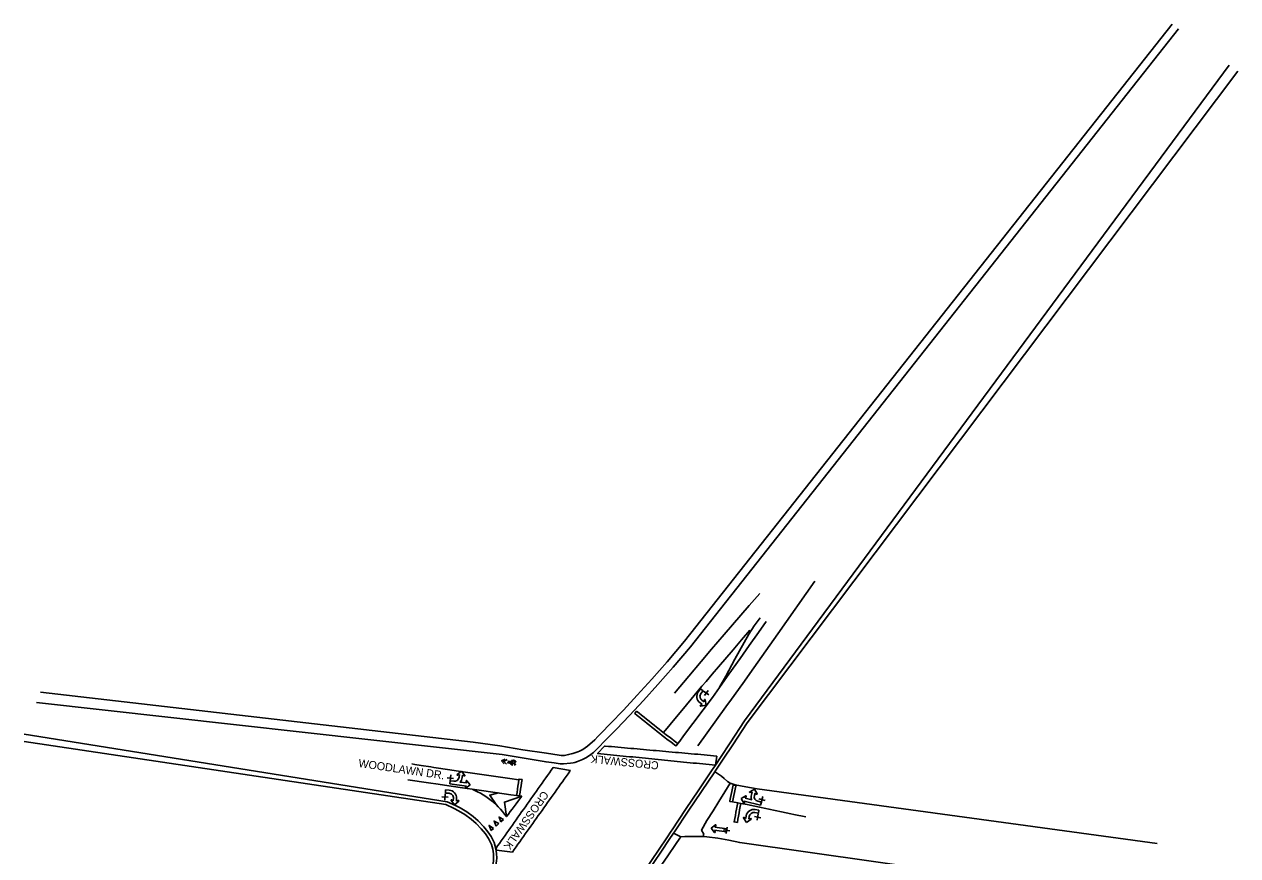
# Model space of a CAD drawing. Extents: x 1729281 to 1732101, y 650763 to 653805.
# Drawn here: x 1730328 to 1731086, y 653286 to 653805 of the extents above; entities that cross this region are included whole.
import ezdxf

# ---------------------------------------------------------------- set-up
doc = ezdxf.new("R2010")
doc.units = 0
for name, color, linetype in [('SURVEY - ROADSIDE BARRIERS with Text', 7, 'Continuous'), ('SURVEY - TRAFFIC CONTROL - Pavement Marking - Points - Locators', 7, 'Continuous'), ('SURVEY - TRAFFIC CONTROL - Pavement Marking with Text', 7, 'Continuous'), ('SURVEY - TRANSPORTATION - Features', 7, 'Continuous'), ('SURVEY - TRANSPORTATION - Roads', 7, 'Continuous'), ('SURVEY - TRANSPORTATION - Roads Text', 7, 'Continuous')]:
    doc.layers.add(name, color=color, linetype=linetype)

msp = doc.modelspace()

# ---------------------------------------------------------------- linework, layer by layer
at = {"layer": 'SURVEY - ROADSIDE BARRIERS with Text'}
for points in [[(1730663.16, 653348.86), (1730665.26, 653348.91), (1730667.81, 653349.44), (1730669.47, 653349.82), (1730670.44, 653350.07), (1730671.64, 653350.44), (1730673.67, 653351.24), (1730674.6, 653351.61), (1730676.69, 653352.62), (1730679.7, 653354.72), (1730684.19, 653358.62), (1730686.11, 653360.64), (1730688.16, 653362.79), (1730694.02, 653368.8), (1730702.16, 653377.27), (1730710.73, 653386.5), (1730719.92, 653396.51), (1730729.49, 653407.31), (1730740.14, 653420.16), (1731044.8, 653805.48)], [(1731085.84, 653776.25), (1730779.43, 653369.32), (1730770.36, 653355.57), (1730764.42, 653346.65), (1730759.8, 653339.63), (1730759.25, 653338.77), (1730750.93, 653326.43), (1730742.52, 653314.01), (1730734.03, 653301.24), (1730733.39, 653300.36), (1730730.72, 653296.31), (1730725.93, 653289.21), (1730716.21, 653275.07)], [(1730337.82, 653388.41), (1730608.3, 653357.12), (1730624.79, 653354.98), (1730639.27, 653352.49), (1730654.1, 653350.23), (1730661.91, 653349.02), (1730663.16, 653348.86)], [(1730614.71, 653267.4), (1730616.59, 653270.23), (1730617.64, 653272.3), (1730618.98, 653275.43), (1730619.91, 653278.38), (1730620.45, 653280.88), (1730620.86, 653282.91), (1730620.96, 653284.51), (1730620.97, 653287.52), (1730620.53, 653290.44), (1730619.7, 653293.26), (1730617.79, 653297.02), (1730615.82, 653299.96), (1730613.2, 653303.08), (1730610.03, 653306.4), (1730606.9, 653309.12), (1730602.9, 653312.06), (1730599.11, 653314.37), (1730596.37, 653315.86), (1730591.15, 653318.2), (1730327.77, 653357.56)], [(1730768.85, 653331.69), (1730771.9, 653330.52), (1730778.64, 653329.27), (1730785.53, 653328.14), (1731035.47, 653293.97)], [(1730751.98, 653298.19), (1730754.27, 653298.03), (1730761.02, 653297.22), (1730767.88, 653295.95), (1730774.71, 653294.52), (1731029.66, 653258.33)]]:
    msp.add_lwpolyline(points, dxfattribs=at)
at = {"layer": 'SURVEY - TRAFFIC CONTROL - Pavement Marking - Points - Locators'}
for p, q in [((1730752.63, 653386.28), (1730754.98, 653389.52)), ((1730755.42, 653386.72), (1730752.19, 653389.08)), ((1730594.26, 653336.74), (1730593.75, 653332.77)), ((1730595.99, 653334.51), (1730592.02, 653335.01)), ((1730592.68, 653322.84), (1730588.68, 653323.09)), ((1730590.8, 653324.96), (1730590.56, 653320.97)), ((1730786.73, 653321.83), (1730790.6, 653320.83)), ((1730788.16, 653319.4), (1730789.16, 653323.27)), ((1730783.99, 653310.74), (1730787.92, 653310.04)), ((1730785.6, 653308.42), (1730786.31, 653312.36)), ((1730764.59, 653302.42), (1730768.56, 653301.89)), ((1730766.31, 653300.17), (1730766.84, 653304.14))]:
    msp.add_line(p, q, dxfattribs=at)
at = {"layer": 'SURVEY - TRAFFIC CONTROL - Pavement Marking with Text'}
for p, q in [((1730750.22, 653390.5), (1730748.87, 653388.65)), ((1730751.81, 653389.35), (1730750.22, 653390.5)), ((1730751.81, 653389.35), (1730750.46, 653387.49)), ((1730751.12, 653383.37), (1730752.42, 653382.42)), ((1730752.42, 653382.42), (1730752.71, 653383.61)), ((1730753.72, 653380.26), (1730753.19, 653383.59)), ((1730749.96, 653381.77), (1730751.27, 653380.82)), ((1730751.27, 653380.82), (1730750.22, 653380.18)), ((1730753.72, 653380.26), (1730750.38, 653379.73)), ((1730600.84, 653339.1), (1730598.17, 653337.03)), ((1730599.57, 653336.92), (1730598.38, 653336.6)), ((1730599.36, 653335.32), (1730599.57, 653336.92)), ((1730600.84, 653339.1), (1730602.91, 653336.43)), ((1730601.32, 653335.07), (1730601.52, 653336.68)), ((1730601.52, 653336.68), (1730602.59, 653336.07)), ((1730593.79, 653333.05), (1730593.54, 653331.1)), ((1730593.54, 653331.1), (1730603.97, 653329.77)), ((1730593.79, 653333.05), (1730596.06, 653332.76)), ((1730599.97, 653332.27), (1730604.22, 653331.73)), ((1730603.97, 653329.77), (1730603.36, 653328.71)), ((1730606.39, 653330.46), (1730603.72, 653328.39)), ((1730604.22, 653331.73), (1730603.9, 653332.91)), ((1730606.39, 653330.46), (1730604.33, 653333.13)), ((1730590.83, 653325.42), (1730590.95, 653327.38)), ((1730590.83, 653325.42), (1730593.12, 653325.28)), ((1730590.95, 653327.38), (1730593.24, 653327.24)), ((1730595.89, 653322.15), (1730595.79, 653320.54)), ((1730597.85, 653322.03), (1730597.75, 653320.42)), ((1730638.59, 653323.42), (1730637.1, 653323.63)), ((1730775.56, 653321.95), (1730778.47, 653323.66)), ((1730775.56, 653321.95), (1730777.28, 653319.04)), ((1730778.06, 653322.32), (1730778.8, 653323.3)), ((1730782.2, 653321.25), (1730778.06, 653322.32)), ((1730783.93, 653327.91), (1730781.02, 653326.2)), ((1730782.4, 653325.92), (1730781.18, 653325.75)), ((1730781.99, 653324.35), (1730782.4, 653325.92)), ((1730783.9, 653323.86), (1730784.3, 653325.42)), ((1730783.93, 653327.91), (1730785.64, 653325)), ((1730784.3, 653325.42), (1730785.28, 653324.68)), ((1730596.63, 653318.16), (1730594.39, 653320.69)), ((1730595.79, 653320.54), (1730594.68, 653321.08)), ((1730596.63, 653318.16), (1730599.16, 653320.4)), ((1730597.75, 653320.42), (1730598.92, 653320.82)), ((1730770.28, 653319.9), (1730773.54, 653319.32)), ((1730787.74, 653317.78), (1730777.56, 653320.42)), ((1730777.56, 653320.42), (1730777.73, 653319.2)), ((1730786.73, 653314.75), (1730784.47, 653315.15)), ((1730788.24, 653319.68), (1730786.01, 653320.26)), ((1730786.39, 653312.81), (1730786.73, 653314.75)), ((1730788.24, 653319.68), (1730787.74, 653317.78)), ((1730624.25, 653306.31), (1730622.47, 653304.75)), ((1730627.21, 653308.93), (1730625.49, 653307.41)), ((1730779.04, 653307.13), (1730777.11, 653309.9)), ((1730778.48, 653309.58), (1730777.45, 653310.25)), ((1730778.77, 653311.18), (1730778.48, 653309.58)), ((1730779.04, 653307.13), (1730781.81, 653309.06)), ((1730780.7, 653310.83), (1730780.42, 653309.24)), ((1730780.42, 653309.24), (1730781.62, 653309.5)), ((1730786.39, 653312.81), (1730784.13, 653313.22)), ((1730620.9, 653303.36), (1730619.51, 653302.13)), ((1730756.82, 653303.47), (1730759.51, 653305.52)), ((1730756.82, 653303.47), (1730758.87, 653300.79)), ((1730766.44, 653301.18), (1730758.99, 653302.19)), ((1730758.99, 653302.19), (1730759.3, 653301)), ((1730759.25, 653304.14), (1730759.87, 653305.2)), ((1730766.71, 653303.13), (1730759.25, 653304.14)), ((1730766.44, 653301.18), (1730766.71, 653303.13))]:
    msp.add_line(p, q, dxfattribs=at)
for points in [[(1730748.51, 653354.94), (1730754.39, 653363.03), (1730766.12, 653379.23), (1730769.64, 653384.09), (1730776.66, 653393.82), (1730783.54, 653403.64), (1730798.47, 653424.93), (1730821.64, 653457.63)], [(1730733.93, 653387.8), (1730742.97, 653398.49), (1730750.73, 653407.64), (1730757.2, 653415.26), (1730764.98, 653424.4), (1730766.29, 653425.91), (1730768.92, 653428.92), (1730770.23, 653430.43), (1730780.73, 653442.5), (1730787.33, 653450.08)], [(1730762.17, 653391.45), (1730766.15, 653398.39), (1730771.64, 653409.05), (1730777.53, 653419.51), (1730780.52, 653424.71), (1730783.79, 653429.74), (1730787.59, 653434.9)], [(1730736.12, 653356.29), (1730737.3, 653357.9), (1730739.68, 653361.12), (1730757.62, 653385.16), (1730767.98, 653399.58), (1730774.93, 653409.36), (1730780.7, 653417.53), (1730786.45, 653425.72), (1730791.2, 653432.48)], [(1730780.95, 653427.12), (1730775.76, 653421.02), (1730770.58, 653414.93), (1730761.52, 653404.26), (1730757.61, 653399.71), (1730753.71, 653395.15), (1730751.16, 653392.18)], [(1730727.08, 653363.14), (1730728.14, 653364.42), (1730729.41, 653365.96), (1730733.24, 653370.58), (1730739.62, 653378.28), (1730751.16, 653392.18)], [(1730736.12, 653356.29), (1730734.97, 653354.82), (1730734.29, 653355.33), (1730732.69, 653356.54), (1730731.09, 653357.74), (1730729.5, 653358.94), (1730727.9, 653360.15), (1730726.3, 653361.35), (1730724.73, 653362.59), (1730723.18, 653363.84), (1730721.62, 653365.09), (1730720.06, 653366.35), (1730718.5, 653367.6), (1730716.95, 653368.85), (1730715.39, 653370.1), (1730713.83, 653371.36), (1730712.27, 653372.61), (1730710.71, 653373.86), (1730709.16, 653375.11), (1730710.32, 653376.64)], [(1730710.32, 653376.64), (1730711.88, 653375.39), (1730713.44, 653374.13), (1730714.99, 653372.88), (1730716.55, 653371.62), (1730718.1, 653370.37), (1730719.66, 653369.11), (1730721.22, 653367.86), (1730722.77, 653366.6), (1730724.33, 653365.35), (1730725.88, 653364.09), (1730727.45, 653362.85), (1730729.04, 653361.64), (1730730.64, 653360.44), (1730732.23, 653359.23), (1730733.83, 653358.02), (1730735.42, 653356.82), (1730736.12, 653356.29)], [(1730760.42, 653348.53), (1730759.6, 653342.8), (1730757.61, 653343), (1730755.62, 653343.19), (1730753.63, 653343.39), (1730751.64, 653343.59), (1730749.65, 653343.79), (1730747.66, 653343.98), (1730745.67, 653344.18), (1730743.68, 653344.38), (1730741.69, 653344.58), (1730739.7, 653344.77), (1730737.71, 653344.97), (1730735.72, 653345.17), (1730733.73, 653345.37), (1730731.74, 653345.57), (1730729.75, 653345.76), (1730727.76, 653345.96), (1730725.77, 653346.16), (1730723.78, 653346.35), (1730721.79, 653346.55), (1730719.8, 653346.75), (1730717.81, 653346.95), (1730715.82, 653347.15), (1730713.83, 653347.34), (1730711.83, 653347.54), (1730709.84, 653347.74), (1730707.85, 653347.94), (1730705.86, 653348.13), (1730703.87, 653348.33), (1730701.88, 653348.53), (1730699.89, 653348.73), (1730697.9, 653348.92), (1730695.91, 653349.12), (1730693.92, 653349.32), (1730691.93, 653349.52), (1730689.94, 653349.71), (1730687.95, 653349.91), (1730685.96, 653350.11), (1730690.35, 653354.79)], [(1730690.35, 653354.79), (1730690.69, 653354.76), (1730692.69, 653354.58), (1730694.68, 653354.41), (1730696.67, 653354.23), (1730698.66, 653354.05), (1730700.66, 653353.87), (1730702.65, 653353.69), (1730704.64, 653353.52), (1730706.63, 653353.34), (1730708.62, 653353.16), (1730710.62, 653352.98), (1730712.61, 653352.8), (1730714.6, 653352.63), (1730716.59, 653352.45), (1730718.58, 653352.27), (1730720.58, 653352.09), (1730722.57, 653351.91), (1730724.56, 653351.74), (1730726.55, 653351.56), (1730728.54, 653351.38), (1730730.54, 653351.2), (1730732.53, 653351.02), (1730734.52, 653350.84), (1730736.51, 653350.67), (1730738.51, 653350.49), (1730740.5, 653350.31), (1730742.49, 653350.13), (1730744.48, 653349.95), (1730746.48, 653349.78), (1730748.47, 653349.6), (1730750.46, 653349.42), (1730752.45, 653349.24), (1730754.44, 653349.07), (1730756.44, 653348.89), (1730758.43, 653348.71), (1730760.42, 653348.53)], [(1730627.48, 653343.58), (1730625.94, 653345.53), (1730628.15, 653346.68)], [(1730628.95, 653343.36), (1730627.3, 653345.22), (1730629.51, 653346.37)], [(1730633.24, 653343.38), (1730630.37, 653344.2), (1730629.7, 653344.39), (1730629.76, 653344.55)], [(1730629.93, 653345.15), (1730630.01, 653345.36), (1730630.08, 653345.53)], [(1730633.12, 653344.49), (1730630.81, 653345.19), (1730630.01, 653345.36)], [(1730633.12, 653344.49), (1730630.37, 653344.2), (1730630.81, 653345.19), (1730633.43, 653345.26)], [(1730633.84, 653342.83), (1730634.4, 653343.02), (1730634.54, 653343.16), (1730634.66, 653343.38), (1730634.54, 653343.58), (1730634.3, 653343.79), (1730633.53, 653343.94), (1730632.88, 653343.98), (1730632.21, 653343.94), (1730631.79, 653343.74), (1730631.72, 653343.43), (1730632.25, 653343.05), (1730632.93, 653342.9)], [(1730632.66, 653344.95), (1730632.28, 653345.14), (1730632.28, 653345.14), (1730632.25, 653345.65), (1730632.71, 653345.84), (1730633.34, 653345.89), (1730633.99, 653345.77), (1730634.49, 653345.5), (1730634.79, 653345.19), (1730634.79, 653345.19), (1730634.77, 653344.96), (1730634.52, 653344.73), (1730634.04, 653344.73), (1730633.51, 653344.78)], [(1730569.82, 653343.56), (1730571.79, 653343.26), (1730575.75, 653342.66), (1730581.68, 653341.76), (1730583.65, 653341.46), (1730593.53, 653339.96), (1730597.49, 653339.36), (1730631.11, 653334.46), (1730636.79, 653333.62)], [(1730668.98, 653339.56), (1730658.13, 653341.36), (1730656.98, 653339.73), (1730655.82, 653338.09), (1730654.67, 653336.46), (1730653.52, 653334.83), (1730652.36, 653333.2), (1730651.21, 653331.56), (1730650.05, 653329.93), (1730648.9, 653328.3), (1730647.74, 653326.66), (1730646.59, 653325.03), (1730645.43, 653323.4), (1730644.28, 653321.76), (1730643.12, 653320.13), (1730641.97, 653318.5), (1730640.81, 653316.87), (1730639.66, 653315.23), (1730638.5, 653313.6), (1730637.35, 653311.97), (1730636.19, 653310.33), (1730635.04, 653308.7), (1730633.89, 653307.07), (1730632.73, 653305.43), (1730631.58, 653303.8), (1730630.42, 653302.17), (1730629.27, 653300.54), (1730628.11, 653298.9), (1730626.96, 653297.27), (1730625.8, 653295.64), (1730624.65, 653294), (1730623.49, 653292.37), (1730622.5, 653290.96)], [(1730622.5, 653290.96), (1730622.83, 653289.65), (1730632.68, 653288.51), (1730633.83, 653290.14), (1730634.99, 653291.77), (1730636.15, 653293.4), (1730637.31, 653295.03), (1730638.47, 653296.66), (1730639.63, 653298.29), (1730640.79, 653299.92), (1730641.95, 653301.55), (1730643.11, 653303.18), (1730644.27, 653304.81), (1730645.42, 653306.44), (1730646.58, 653308.07), (1730647.74, 653309.7), (1730648.9, 653311.33), (1730650.06, 653312.95), (1730651.22, 653314.58), (1730652.38, 653316.21), (1730653.54, 653317.84), (1730654.7, 653319.47), (1730655.85, 653321.1), (1730657.01, 653322.73), (1730658.17, 653324.36), (1730659.33, 653325.99), (1730660.49, 653327.62), (1730661.65, 653329.25), (1730662.81, 653330.88), (1730663.97, 653332.51), (1730665.13, 653334.14), (1730666.29, 653335.77), (1730667.45, 653337.4), (1730668.6, 653339.03), (1730668.98, 653339.56)], [(1730567.37, 653333.73), (1730580.39, 653331.8), (1730586.32, 653330.93), (1730590.27, 653330.32), (1730600.15, 653328.82), (1730612.02, 653327.15), (1730621.92, 653325.79), (1730631.81, 653324.37), (1730635.31, 653323.87)], [(1730637.1, 653323.63), (1730635.31, 653323.87), (1730635.61, 653325.84), (1730635.91, 653327.82), (1730636.21, 653329.8), (1730636.51, 653331.78), (1730636.81, 653333.75), (1730636.86, 653334.12), (1730638.77, 653333.81)], [(1730638.77, 653333.81), (1730638.45, 653331.84), (1730638.12, 653329.87), (1730637.8, 653327.9), (1730637.48, 653325.92), (1730637.15, 653323.95), (1730637.1, 653323.63)], [(1730772.29, 653330.13), (1730770.58, 653330.38), (1730770.19, 653328.42), (1730769.79, 653326.46), (1730769.4, 653324.5), (1730769.01, 653322.54), (1730768.62, 653320.58), (1730768.53, 653320.16), (1730770.28, 653319.9)], [(1730770.28, 653319.9), (1730770.67, 653321.87), (1730771.05, 653323.83), (1730771.44, 653325.79), (1730771.82, 653327.75), (1730772.2, 653329.71), (1730772.29, 653330.13)], [(1730608.06, 653327.67), (1730609.21, 653327.08), (1730610.99, 653326.18), (1730612.77, 653325.27), (1730614.5, 653324.26), (1730616.17, 653323.17), (1730617.84, 653322.07), (1730619.43, 653320.87), (1730621, 653319.63), (1730622.51, 653318.33), (1730623.87, 653316.87), (1730625.23, 653315.41), (1730626.5, 653313.87), (1730627.76, 653312.32), (1730629.02, 653310.77), (1730630.22, 653312.21), (1730631.42, 653313.81), (1730632.61, 653315.41), (1730633.81, 653317.01), (1730635.01, 653318.62), (1730636.2, 653320.22), (1730637.4, 653321.82), (1730638.59, 653323.42)], [(1730622.51, 653318.33), (1730618.56, 653324.2), (1730623.94, 653325.5)], [(1730629.08, 653310.69), (1730627.69, 653319.77), (1730638.59, 653323.42)], [(1730773.54, 653319.32), (1730773.16, 653317.36), (1730772.78, 653315.39), (1730772.4, 653313.43), (1730772.02, 653311.47), (1730771.65, 653309.51), (1730771.24, 653307.42), (1730773.29, 653307.13)], [(1730773.29, 653307.13), (1730773.63, 653309.1), (1730773.98, 653311.07), (1730774.33, 653313.04), (1730774.67, 653315.01), (1730775.02, 653316.98), (1730775.37, 653318.99), (1730773.54, 653319.32)], [(1730775.37, 653318.99), (1730779.28, 653318.2), (1730781.24, 653317.8), (1730787.1, 653316.62), (1730791.01, 653315.83), (1730792.96, 653315.43), (1730800.77, 653313.79), (1730806.62, 653312.54), (1730808.57, 653312.12), (1730816.02, 653310.52)], [(1730622.47, 653304.75), (1730621.3, 653307.88), (1730624.25, 653306.31)], [(1730625.49, 653307.41), (1730624.44, 653310.38), (1730627.21, 653308.93)], [(1730619.51, 653302.13), (1730618.17, 653305.21), (1730620.9, 653303.36)]]:
    msp.add_lwpolyline(points, dxfattribs=at)
for centre, radius, start, end in [((1730752.85, 653385.75), 4.92, 143.97128, 233.97128), ((1730752.85, 653385.75), 2.95, 143.97128, 233.97128), ((1730752.95, 653383.55), 0.246, 8.97128, 166.46444), ((1730750.35, 653379.97), 0.246, 121.52301, 278.97128), ((1730598.32, 653336.84), 0.246, 127.74242, 285.23558), ((1730602.71, 653336.28), 0.246, 240.29416, 37.74242), ((1730596.44, 653335.69), 2.95, 262.74242, 352.74242), ((1730596.44, 653335.69), 4.92, 315.87252, 352.74242), ((1730604.13, 653332.98), 0.246, 37.74242, 195.23558), ((1730592.94, 653322.33), 2.95, 356.49532, 86.49532), ((1730592.94, 653322.33), 4.92, 356.49532, 86.49532), ((1730603.57, 653328.58), 0.246, 150.29416, 307.74242), ((1730778.6, 653323.45), 0.246, 322.98548, 120.47865), ((1730781.14, 653325.99), 0.246, 120.47865, 277.92691), ((1730786.75, 653323.12), 4.92, 165.47865, 202.34854), ((1730786.75, 653323.12), 2.95, 165.47865, 255.47865), ((1730785.43, 653324.88), 0.246, 232.98548, 30.47865), ((1730594.58, 653320.86), 0.246, 64.00216, 221.49532), ((1730599, 653320.59), 0.246, 311.49532, 108.94358), ((1730777.49, 653319.16), 0.246, 210.47865, 7.92691), ((1730783.61, 653310.31), 4.92, 79.87444, 169.87444), ((1730777.31, 653310.04), 0.246, 57.42618, 214.87444), ((1730783.61, 653310.31), 2.95, 79.87444, 169.87444), ((1730781.67, 653309.26), 0.246, 304.87444, 102.3676), ((1730759.07, 653300.94), 0.246, 217.31514, 14.8083), ((1730759.66, 653305.32), 0.246, 329.86687, 127.31514)]:
    msp.add_arc(centre, radius, start, end, dxfattribs=at)
at = {"layer": 'SURVEY - TRANSPORTATION - Features'}
for points in [[(1730763.39, 653336.05), (1730759.63, 653338.52), (1730759.25, 653338.77)], [(1730751.98, 653298.19), (1730752.4, 653299.84), (1730750.91, 653302.16), (1730754.28, 653308.34), (1730758.04, 653314.24), (1730761.69, 653320.22), (1730765.35, 653326.19), (1730768.85, 653331.69)], [(1730768.85, 653331.69), (1730767.13, 653332.72), (1730765.03, 653334.43), (1730763.39, 653336.05)], [(1730733.39, 653300.36), (1730733.75, 653300.08), (1730737.97, 653298.15)], [(1730737.97, 653298.15), (1730737.38, 653297.24), (1730734.67, 653293.21), (1730729.82, 653286.16), (1730720.1, 653272.02), (1730705.64, 653247.38), (1730698.15, 653234.38), (1730690.58, 653221.43), (1730678.7, 653200.97), (1730663.77, 653174.94), (1730649.34, 653150.02), (1730641.83, 653136.99), (1730639.85, 653133.62), (1730630.65, 653117.34), (1730616.96, 653090.7), (1730604.4, 653063.52), (1730598.78, 653049.61)], [(1730737.97, 653298.15), (1730740.4, 653298.28), (1730747.29, 653298.36), (1730751.98, 653298.19)]]:
    msp.add_lwpolyline(points, dxfattribs=at)
at = {"layer": 'SURVEY - TRANSPORTATION - Roads'}
for points in [[(1730335.35, 653381.9), (1730626.29, 653349.44), (1730649.97, 653345.55), (1730653.8, 653344.9), (1730658.77, 653344.22), (1730662.63, 653343.58), (1730664.74, 653343.64), (1730668.99, 653344), (1730670.66, 653344.29), (1730671.63, 653344.55), (1730673.48, 653345.14), (1730675.52, 653345.93), (1730676.44, 653346.31), (1730678.53, 653347.31), (1730680.9, 653348.82), (1730683.28, 653350.79), (1730687.57, 653354.91), (1730689.48, 653356.93), (1730691.6, 653359.01), (1730697.83, 653365.4), (1730705.97, 653373.87), (1730714.53, 653383.12), (1730723.67, 653393.17), (1730733.24, 653403.96), (1730743.89, 653416.82), (1731048.78, 653802.65)], [(1731080.5, 653780.05), (1730777.76, 653370.42), (1730768.67, 653356.68), (1730762.82, 653347.7), (1730759.6, 653342.8), (1730758.15, 653340.72), (1730757.59, 653339.86), (1730749.27, 653327.53), (1730740.9, 653315.08), (1730732.5, 653302.44), (1730731.87, 653301.56), (1730729.19, 653297.5), (1730724.4, 653290.41), (1730714.81, 653276.16), (1730699.21, 653251.24), (1730692.6, 653239.86)], [(1730616.87, 653266.71), (1730618.46, 653269.56), (1730619.5, 653271.64), (1730620.85, 653274.76), (1730621.78, 653277.7), (1730622.32, 653280.2), (1730622.84, 653283.07), (1730622.93, 653284.68), (1730622.7, 653287.67), (1730622.42, 653290.6), (1730621.29, 653294.51), (1730619.4, 653298.27), (1730617.42, 653301.21), (1730614.79, 653304.32), (1730611.29, 653307.98), (1730608.15, 653310.7), (1730604.15, 653313.63), (1730599.99, 653316.18), (1730597.25, 653317.67), (1730592.03, 653320.02), (1730327.8, 653362.26)]]:
    msp.add_lwpolyline(points, dxfattribs=at)

# ---------------------------------------------------------------- texts
at = {"layer": 'SURVEY - TRAFFIC CONTROL - Pavement Marking with Text'}
for rotation, p in [(174.31792, (1730724.34, 653345.03)), (234.74525, (1730651.69, 653327.22))]:
    msp.add_text('CROSSWALK', height=5, rotation=rotation, dxfattribs=at).set_placement(p)
at = {"layer": 'SURVEY - TRANSPORTATION - Roads Text'}
msp.add_text('WOODLAWN DR.', height=5, rotation=351.70605, dxfattribs=at).set_placement((1730536.3, 653341.74))

doc.saveas('drawing.dxf')
